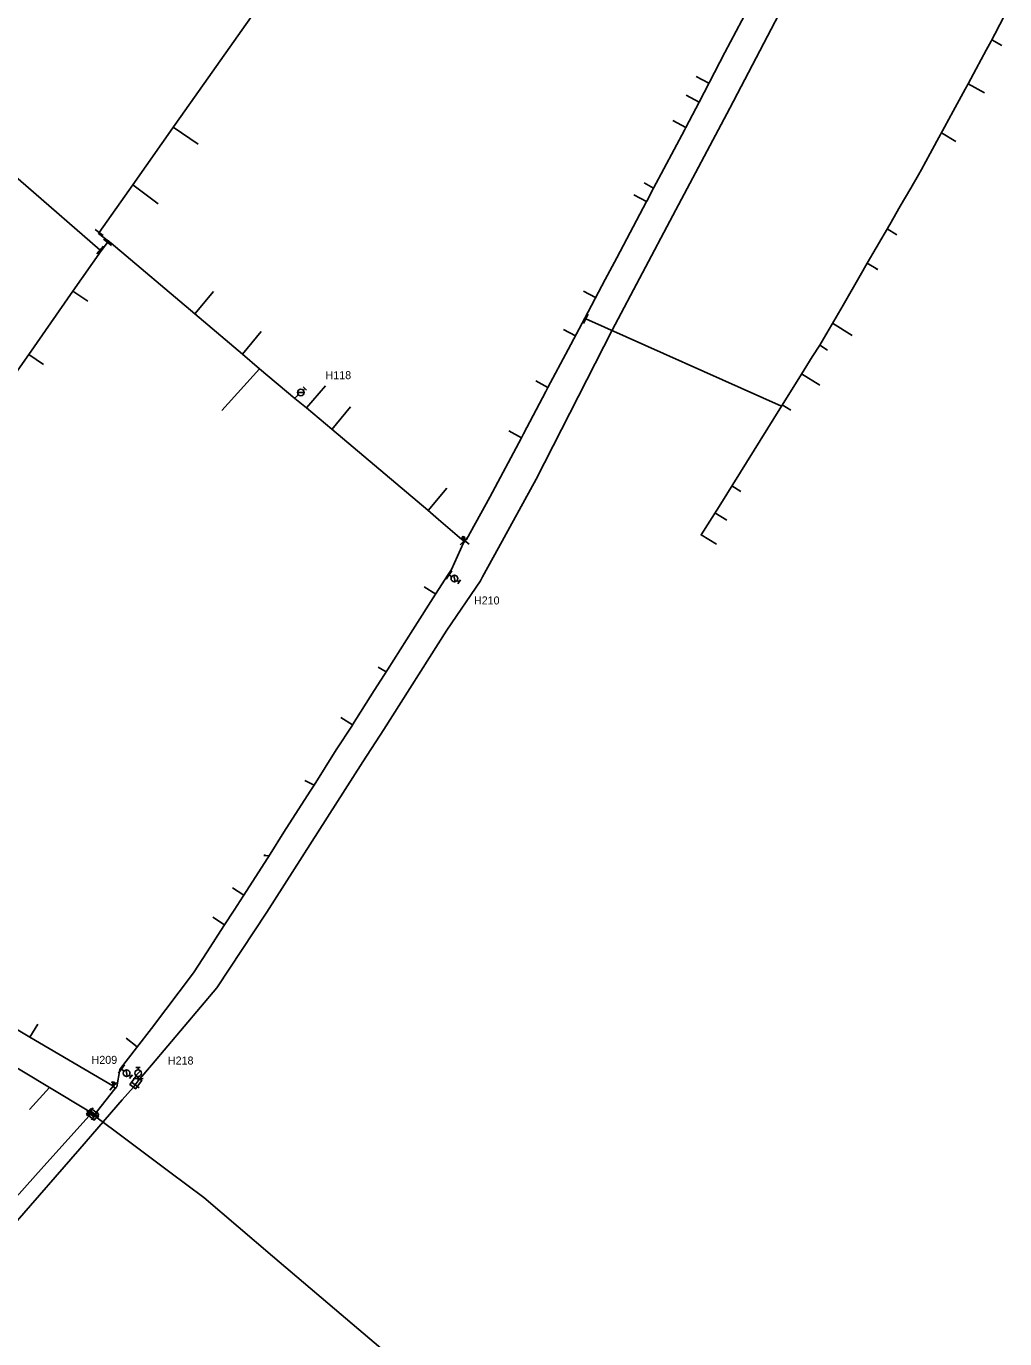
# Model space of a CAD drawing. Extents: x -548873 to -538270, y -1201997 to -1192514.
# Drawn here: x -544006.3 to -543761.7, y -1193175.5 to -1192847.4 of the extents above; entities that cross this region are included whole.
import ezdxf

# ---------------------------------------------------------------- set-up
doc = ezdxf.new("R2010")
doc.units = 0
for name, color, linetype in [('KN_HRAN_STÁTNÍ', 7, 'Continuous'), ('KN_PARC_Č', 7, 'Continuous'), ('KN_VKP_HRAN_SPORNÁ', 7, 'Continuous'), ('PK_PARC_Čv', 7, 'Continuous'), ('Vrstva 29', 7, 'Continuous'), ('Vrstva 39', 7, 'Continuous')]:
    doc.layers.add(name, color=color, linetype=linetype)

# ---------------------------------------------------------------- blocks, each defined once
blk = doc.blocks.new('160')
at = {"layer": 'KN_HRAN_STÁTNÍ'}
blk.add_circle((0, 0), 0.0458, dxfattribs=at)
blk = doc.blocks.new('147')
at = {"layer": 'KN_HRAN_STÁTNÍ'}
blk.add_line((0, 1.27), (0, -1.27), dxfattribs=at)
blk = doc.blocks.new('133')
at = {"layer": 'KN_HRAN_STÁTNÍ'}
for p, q in [((0.28, 0), (0, 0)), ((0.54, 0.58), (1.7, -0.58)), ((1.94, 0), (2.52, 0)), ((2.52, 0.58), (2.52, -0.58))]:
    blk.add_line(p, q, dxfattribs=at)
blk.add_circle((1.11, 0), 0.825, dxfattribs=at)
blk = doc.blocks.new('150')
at = {"layer": 'KN_HRAN_STÁTNÍ'}
blk.add_line((0, 1.27), (0, -1.27), dxfattribs=at)
blk = doc.blocks.new('128')
at = {"layer": 'KN_HRAN_STÁTNÍ'}
for p, q in [((-0.19, 1.06), (-0.43, 1.15)), ((-0.36, 0.84), (-0.19, 1.06)), ((-0.19, 1.06), (-0.02, 1.25)), ((-0.19, 1.06), (0, 0)), ((0.05, 0.95), (-0.19, 1.06)), ((-0.1, 1), (0.41, 0.91)), ((-0.07, 0.82), (0.17, 0.96)), ((0.17, 0.96), (-0.02, 1.13)), ((0.17, 0.96), (0, 0)), ((0.19, 1.21), (0.17, 0.96)), ((0.17, 0.96), (0.38, 1.08)), ((0.36, 0.77), (0.17, 0.96))]:
    blk.add_line(p, q, dxfattribs=at)

msp = doc.modelspace()

# ---------------------------------------------------------------- linework, layer by layer
at = {"layer": 'KN_PARC_Č'}
for points in [[(-543764.899, -1192850.757), (-543762.401, -1192852.222)], [(-543835.638, -1192861.643), (-543838.843, -1192859.951)], [(-543770.862, -1192861.752), (-543766.739, -1192864.022)], [(-543838.077, -1192866.33), (-543841.299, -1192864.649)], [(-543841.373, -1192872.664), (-543844.618, -1192870.949)], [(-543969.525, -1192872.585), (-543963.331, -1192876.858)], [(-543777.508, -1192873.988), (-543773.931, -1192876.224)], [(-543979.677, -1192887.046), (-543973.281, -1192891.776)], [(-543849.469, -1192887.872), (-543851.85, -1192886.547)], [(-543851.239, -1192891.193), (-543854.391, -1192889.537)], [(-543791.054, -1192898.028), (-543788.62, -1192899.502)], [(-543796.042, -1192906.636), (-543793.376, -1192908.178)], [(-543793.636, -1192908.028), (-543793.753, -1192908.304)], [(-543994.599, -1192913.632), (-543990.9, -1192916.131)], [(-543964.148, -1192919.298), (-543959.482, -1192913.696)], [(-543863.952, -1192915.207), (-543866.969, -1192913.615)], [(-543868.967, -1192924.735), (-543871.979, -1192923.163)], [(-543804.74, -1192921.647), (-543799.792, -1192924.65)], [(-543952.247, -1192929.357), (-543947.535, -1192923.704)], [(-544005.63, -1192929.441), (-544001.954, -1192931.973)], [(-543807.947, -1192927.066), (-543805.989, -1192928.318)], [(-543947.936, -1192933.001), (-543957.378, -1192943.474)], [(-543875.871, -1192937.689), (-543878.895, -1192936.063)], [(-543812.45, -1192934.286), (-543807.868, -1192937.077)], [(-543936.268, -1192942.814), (-543931.49, -1192937.237)], [(-543929.92, -1192948.153), (-543925.202, -1192942.505)], [(-543817.293, -1192942.05), (-543815.144, -1192943.39)], [(-543882.493, -1192950.284), (-543885.674, -1192948.546)], [(-543905.848, -1192968.4), (-543901.138, -1192962.893)], [(-543829.919, -1192962.294), (-543827.675, -1192963.728)], [(-543834.124, -1192969.037), (-543831.152, -1192970.832)], [(-543837.541, -1192974.515), (-543833.746, -1192976.835)], [(-543903.935, -1192989.331), (-543906.79, -1192987.513)], [(-543916.305, -1193008.804), (-543918.3, -1193007.577)], [(-543924.692, -1193022.046), (-543927.627, -1193020.171)], [(-543934.349, -1193037.078), (-543936.61, -1193035.91)], [(-543945.565, -1193054.733), (-543946.863, -1193054.719)], [(-543946.634, -1193054.721), (-543946.684, -1193054.447)], [(-543951.861, -1193064.611), (-543954.716, -1193062.759)], [(-543956.689, -1193071.994), (-543959.643, -1193070.1)], [(-544005.383, -1193100.056), (-544003.39, -1193096.869)], [(-543978.574, -1193102.517), (-543981.336, -1193100.366)], [(-544000.466, -1193112.661), (-544005.429, -1193118.186)]]:
    msp.add_lwpolyline(points, dxfattribs=at)
at = {"layer": 'KN_VKP_HRAN_SPORNÁ'}
for points in [[(-543988.04, -1192898.96), (-543979.677, -1192887.046), (-543969.055, -1192871.915), (-543964.242, -1192865.115), (-543948.948, -1192843.507), (-543936.009, -1192825.225), (-543926.274, -1192811.472), (-543924.182, -1192808.516), (-543917.149, -1192798.442), (-543912.747, -1192792.142), (-543905.218, -1192781.352), (-543902.251, -1192777.113), (-543899.603, -1192773.309), (-543894.887, -1192766.568), (-543892.602, -1192763.296), (-543868.371, -1192727.545), (-543858.752, -1192711.53)], [(-543783.015, -1192764.347), (-543783.274, -1192764.879), (-543785.89, -1192769.88), (-543788.15, -1192771.39), (-543789.32, -1192773.57), (-543792.94, -1192780.44), (-543798.219, -1192790.022), (-543808.404, -1192809.611), (-543811.18, -1192814.95), (-543817.772, -1192827.521), (-543820.44, -1192832.61), (-543822.823, -1192837.155), (-543826.03, -1192843.27), (-543831.64, -1192853.96), (-543838.077, -1192866.33), (-543841.373, -1192872.664), (-543841.74, -1192873.37), (-543849.469, -1192887.872), (-543851.19, -1192891.1), (-543851.239, -1192891.193), (-543858.64, -1192905.27), (-543861.61, -1192910.71), (-543866.65, -1192920.39)], [(-544152.325, -1192768.497), (-544151.575, -1192769.223), (-544140.519, -1192773.507), (-544125.419, -1192785.798), (-544105.532, -1192802.494), (-544103.571, -1192804.167), (-544096.951, -1192809.816), (-544075.452, -1192828.159), (-544073.508, -1192829.818), (-544071.137, -1192831.841), (-544068.144, -1192834.394), (-544066.8, -1192835.541), (-544049.831, -1192850.013), (-544045.643, -1192853.585), (-544031.857, -1192865.343), (-544025.774, -1192870.531), (-544018.921, -1192876.449), (-544006.358, -1192887.169), (-543987.78, -1192903.34)], [(-543978.302, -1193111.017), (-543977.92, -1193110.518), (-543974.99, -1193107.06), (-543958.629, -1193087.753), (-543946.124, -1193068.848), (-543922.134, -1193031.305), (-543916.932, -1193023.165), (-543901.182, -1192998.372), (-543892.761, -1192986.013), (-543892.217, -1192985.029), (-543888.198, -1192977.759), (-543878.838, -1192960.586), (-543859.8, -1192923.356), (-543852.208, -1192909.028), (-543844.617, -1192894.701), (-543830.409, -1192867.833), (-543807.844, -1192824.632), (-543782.269, -1192775.669)], [(-543817.474, -1192942.341), (-543813.16, -1192935.424), (-543809.805, -1192930.045), (-543807.947, -1192927.066), (-543807.011, -1192925.565), (-543806.146, -1192924.072), (-543802.088, -1192917.069), (-543797.802, -1192909.672), (-543796.042, -1192906.636), (-543793.795, -1192902.759), (-543790.408, -1192896.913), (-543787.791, -1192892.396), (-543785.165, -1192887.865), (-543783.242, -1192884.546), (-543782.521, -1192883.218), (-543780.356, -1192879.232), (-543778.64, -1192876.072), (-543776.743, -1192872.58), (-543774.57, -1192868.58), (-543771.592, -1192863.096), (-543770.862, -1192861.752), (-543768.844, -1192858.036), (-543766.327, -1192853.401), (-543765.071, -1192851.089), (-543764.899, -1192850.757), (-543764.185, -1192849.375), (-543761.683, -1192844.534)], [(-543985.7, -1192901.081), (-543988.202, -1192899.158), (-543988.04, -1192898.96)], [(-543987.554, -1192903.537), (-543994.599, -1192913.633), (-544005.63, -1192929.441), (-544008.387, -1192933.391), (-544014.091, -1192941.565), (-544021.221, -1192951.705), (-544032.028, -1192967.074), (-544035.944, -1192972.743), (-544038.189, -1192975.993), (-544042.742, -1192982.584), (-544042.929, -1192982.851), (-544045.731, -1192986.825), (-544046.636, -1192988.108), (-544051.935, -1192995.621), (-544052.942, -1192997.05), (-544056.98, -1193002.725), (-544061.78, -1193009.47), (-544061.89, -1193009.624), (-544065.509, -1193014.71), (-544070.961, -1193022.372), (-544075.98, -1193029.639), (-544081.061, -1193036.998), (-544089.427, -1193049.251)], [(-543987.78, -1192903.34), (-543987.554, -1192903.537)], [(-543987.554, -1192903.537), (-543985.947, -1192901.405)], [(-543985.947, -1192901.405), (-543985.7, -1192901.081)], [(-543985.7, -1192901.081), (-543985.055, -1192901.627), (-543964.15, -1192919.296), (-543952.246, -1192929.358), (-543947.936, -1192933.001), (-543939.138, -1192940.401), (-543936.268, -1192942.814), (-543929.93, -1192948.146), (-543905.856, -1192968.393), (-543903.872, -1192970.107), (-543903.228, -1192970.664), (-543897.396, -1192975.704), (-543897.172, -1192975.898), (-543896.96, -1192976.11)], [(-543866.65, -1192920.39), (-543870.81, -1192928.19), (-543875.871, -1192937.689), (-543876.419, -1192938.719), (-543881.96, -1192949.29), (-543882.493, -1192950.284), (-543890.43, -1192965.08), (-543896.26, -1192975.72), (-543896.57, -1192976.04)], [(-543866.65, -1192920.39), (-543866.4, -1192920.52)], [(-543866.4, -1192920.52), (-543817.474, -1192942.341)], [(-543817.474, -1192942.341), (-543833.109, -1192967.409), (-543835.402, -1192971.086), (-543837.541, -1192974.515)], [(-543896.57, -1192976.04), (-543896.76, -1192976.31)], [(-543983.94, -1193112.88), (-543983.63, -1193112.48), (-543982.92, -1193108.18), (-543982.7, -1193107.92), (-543978.75, -1193102.74), (-543974.95, -1193097.92), (-543964.47, -1193084.02), (-543961.06, -1193078.8), (-543956.86, -1193072.26), (-543954.33, -1193068.32), (-543952.04, -1193064.879), (-543951.861, -1193064.611), (-543945.34, -1193054.38), (-543941.88, -1193048.88), (-543935.32, -1193038.6), (-543934.349, -1193037.078), (-543928.77, -1193028.3), (-543924.74, -1193022.12), (-543924.692, -1193022.046), (-543919.28, -1193013.47), (-543915.99, -1193008.31), (-543909.64, -1192998.26), (-543903.963, -1192989.375), (-543900.81, -1192984.44), (-543899.98, -1192983.17), (-543896.97, -1192976.56), (-543896.76, -1192976.31)], [(-543896.96, -1192976.11), (-543896.76, -1192976.31)], [(-544089.596, -1193049.499), (-544063.674, -1193065.21), (-544043.296, -1193077.56), (-544037.046, -1193081.349), (-544022.496, -1193089.945), (-544005.384, -1193100.056), (-543984.659, -1193112.301), (-543984.54, -1193112.42)], [(-544089.577, -1193059.128), (-544080.838, -1193064.37), (-544048.376, -1193083.844), (-544034.709, -1193092.076), (-544000.466, -1193112.661), (-543990.613, -1193118.584), (-543990.374, -1193118.783)], [(-544345.745, -1193444.61), (-544343.348, -1193443.882), (-544324.303, -1193438.096), (-544308.937, -1193423.077), (-544301.353, -1193415.664), (-544300.262, -1193414.734), (-544299.949, -1193414.468), (-544256.263, -1193375.958), (-544244.022, -1193365.058), (-544211.153, -1193335.791), (-544164.9, -1193294.332), (-544162.049, -1193291.777), (-544118.276, -1193252.536), (-544093.677, -1193229.114), (-544073.439, -1193209.843), (-544031.304, -1193170.221), (-544021.493, -1193160.525), (-544009.164, -1193146.705), (-543992.901, -1193127.997), (-543982.272, -1193115.771), (-543979.5, -1193112.583), (-543979.069, -1193112.02)], [(-543989.147, -1193119.368), (-543988.441, -1193118.492), (-543986.287, -1193115.792), (-543984.1, -1193113.05), (-543983.94, -1193112.88)], [(-543984.54, -1193112.42), (-543983.94, -1193112.88)], [(-543979.069, -1193112.02), (-543978.302, -1193111.017)], [(-543990.185, -1193119.36), (-543990.569, -1193119.789), (-544001.851, -1193132.369), (-544011.576, -1193143.213), (-544026.824, -1193160.216), (-544033.682, -1193166.96), (-544037.468, -1193170.683), (-544049.173, -1193181.955), (-544056.195, -1193188.717), (-544060.141, -1193192.517), (-544060.171, -1193192.546), (-544068.739, -1193200.6), (-544078.191, -1193209.486), (-544093.98, -1193224.329), (-544102.083, -1193231.947), (-544119.64, -1193248.654), (-544129.282, -1193258.095), (-544143.756, -1193271.606), (-544151.187, -1193278.063), (-544166.907, -1193291.698)], [(-543990.374, -1193118.783), (-543989.969, -1193119.122)], [(-543989.969, -1193119.122), (-543990.185, -1193119.36)], [(-543989.969, -1193119.122), (-543989.349, -1193119.64)], [(-543989.349, -1193119.64), (-543989.147, -1193119.368)], [(-543989.349, -1193119.64), (-543989.164, -1193119.79)], [(-543989.164, -1193119.79), (-543988.724, -1193120.144), (-543988.525, -1193120.293), (-543984.425, -1193123.357), (-543970.362, -1193133.868), (-543961.93, -1193140.17), (-543944.688, -1193154.831), (-543923.153, -1193173.142), (-543912.732, -1193182.003), (-543910.29, -1193184.08), (-543902.222, -1193193.203), (-543901.5, -1193194.02), (-543887.55, -1193208.94), (-543897.294, -1193225.878), (-543907.211, -1193243.115), (-543910.2, -1193248.31), (-543910.25, -1193249.195), (-543910.3, -1193250.08), (-543909.78, -1193251.7), (-543909.32, -1193251.999), (-543896.323, -1193260.377), (-543890.307, -1193264.257), (-543889.634, -1193264.631)]]:
    msp.add_lwpolyline(points, dxfattribs=at)
at = {"layer": 'PK_PARC_Čv'}
for points in [[(-543939.159, -1192940.383), (-543938.458, -1192939.697)], [(-543900.81, -1192984.44), (-543900.6, -1192984.56), (-543900.183, -1192984.847)], [(-543982.7, -1193107.92), (-543982.49, -1193108.06), (-543982.053, -1193108.417)], [(-543978.794, -1193109.85), (-543977.364, -1193110.944), (-543978.944, -1193113.009), (-543980.374, -1193111.915), (-543978.794, -1193109.85)], [(-543978.302, -1193111.017), (-543978.302, -1193110.188)], [(-543990.041, -1193117.891), (-543988.152, -1193119.451), (-543989.298, -1193120.839), (-543991.187, -1193119.279), (-543990.041, -1193117.891)]]:
    msp.add_lwpolyline(points, dxfattribs=at)

# ---------------------------------------------------------------- block references
for name, p, xscale, yscale, rotation in [('133', (-543938.458, -1192939.697), 0.999999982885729, 0.9999999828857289, 45), ('150', (-543900.6, -1192984.56), 0.9999999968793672, 0.9999999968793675, -32.00000027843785), ('133', (-543900.183, -1192984.847), 0.9999999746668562, 0.999999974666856, -34.00000045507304), ('150', (-543982.49, -1193108.06), 1.000000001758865, 1.000000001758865, -35.99999933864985), ('133', (-543982.053, -1193108.417), 1.000000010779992, 1.0000000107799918, -38.9999989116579), ('150', (-543978.302, -1193110.475), 1.000000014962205, 1.0000000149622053, -89.0000000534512), ('133', (-543978.302, -1193110.188), 1.000000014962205, 1.0000000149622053, 90.99999994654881)]:
    msp.add_blockref(name, p, dxfattribs=dict(at, xscale=xscale, yscale=yscale, rotation=rotation))
at = {"layer": 'Vrstva 29'}
for name, p, xscale, yscale, rotation in [('147', (-543988.04, -1192898.96), 0.9999999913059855, 0.9999999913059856, -127.00000193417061), ('147', (-543987.78, -1192903.34), 1.0000000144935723, 1.0000000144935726, 139.00000089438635), ('160', (-543987.554, -1192903.537), 0.9999999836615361, 0.9999999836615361, 98.00000038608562), ('147', (-543985.947, -1192901.405), 0.9999999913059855, 0.9999999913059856, 52.999998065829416), ('160', (-543985.7, -1192901.081), 1.000000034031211, 1.0000000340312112, -38.000000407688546), ('147', (-543866.4, -1192920.52), 1.0169562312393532, 1.016956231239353, 153.02398354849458), ('160', (-543866.65, -1192920.39), 1.033506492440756, 1.033506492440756, -156.95871826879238), ('160', (-543817.474, -1192942.341), 1.0000000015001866, 1.0000000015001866, -120.99999982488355), ('147', (-543896.96, -1192976.11), 1.0000000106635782, 1.0000000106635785, -44.00000165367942), ('147', (-543896.57, -1192976.04), 1.000000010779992, 1.0000000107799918, -128.99999891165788), ('160', (-543837.541, -1192974.515), 1.0000000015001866, 1.0000000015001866, 59.00000017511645), ('160', (-543896.76, -1192976.31), 0.9999999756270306, 0.9999999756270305, -86.99999998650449), ('147', (-543984.54, -1193112.42), 1.0000000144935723, 1.0000000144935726, 139.00000089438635), ('160', (-543983.94, -1193112.88), 1.0092050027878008, 1.0092050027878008, -168.88308178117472), ('147', (-543979.069, -1193112.02), 0.9999999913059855, 0.9999999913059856, -127.00000193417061), ('160', (-543978.302, -1193111.017), 0.9999999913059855, 0.9999999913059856, -127.00000193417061), ('147', (-543990.374, -1193118.783), 1.000000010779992, 1.0000000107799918, -38.9999989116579), ('147', (-543990.185, -1193119.36), 1.0000000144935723, 1.0000000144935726, -130.99999910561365), ('147', (-543989.147, -1193119.368), 0.9999999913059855, 0.9999999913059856, -127.00000193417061), ('160', (-543989.969, -1193119.122), 1.0000000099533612, 1.0000000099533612, -63.999999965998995), ('147', (-543989.164, -1193119.79), 1.000000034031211, 1.0000000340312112, 141.99999959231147), ('160', (-543989.349, -1193119.64), 1.000000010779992, 1.0000000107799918, 141.00000108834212)]:
    msp.add_blockref(name, p, dxfattribs=dict(at, xscale=xscale, yscale=yscale, rotation=rotation))
at = {"layer": 'Vrstva 39'}
for p in [(-543896.96, -1192976.11), (-543984.54, -1193112.42)]:
    msp.add_blockref('128', p, dxfattribs=at)

# ---------------------------------------------------------------- texts
at = {"layer": 'PK_PARC_Čv'}
for s, p in [('H118', (-543931.458, -1192935.607)), ('H210', (-543894.363, -1192991.927)), ('H209', (-543989.953, -1193106.767)), ('H218', (-543970.872, -1193106.938))]:
    msp.add_text(s, height=2, dxfattribs=at).set_placement(p)

doc.saveas('drawing.dxf')
